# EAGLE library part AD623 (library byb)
Instrumentation Amp Single-Power, Low Cost, Instrumentation Amp
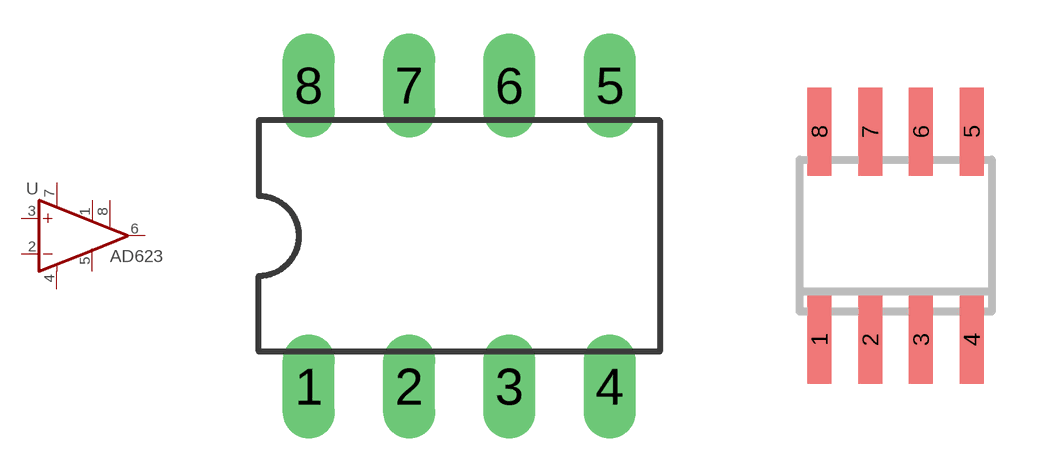
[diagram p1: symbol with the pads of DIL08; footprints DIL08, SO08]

Designator prefix -

## AD623N  [DIL08]
1  GAIN  pas
2  -IN  in
3  +IN  in
4  GND  pwr
5  BYPASS  pas
6  OUT  out
7  VS  pwr
8  GAIN  pas

## AD623R  [SO08]
Pads as for DIL08

## Footprint DIL08 (pad centres in mm)
Dual In Line Package
drill 0.813 pad 1.27 long: 1 -3.81,-3.81; 2 -1.27,-3.81; 3 1.27,-3.81; 4 3.81,-3.81; 5 3.81,3.81; 6 1.27,3.81; 7 -1.27,3.81; 8 -3.81,3.81

## Footprint SO08 (pad centres in mm)
Small Outline Package 8 NS Package M08A
smd 0.6 x 2.2: 1 -1.905,-2.6; 2 -0.635,-2.6; 3 0.635,-2.6; 4 1.905,-2.6; 5 1.905,2.6; 6 0.635,2.6; 7 -0.635,2.6; 8 -1.905,2.6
